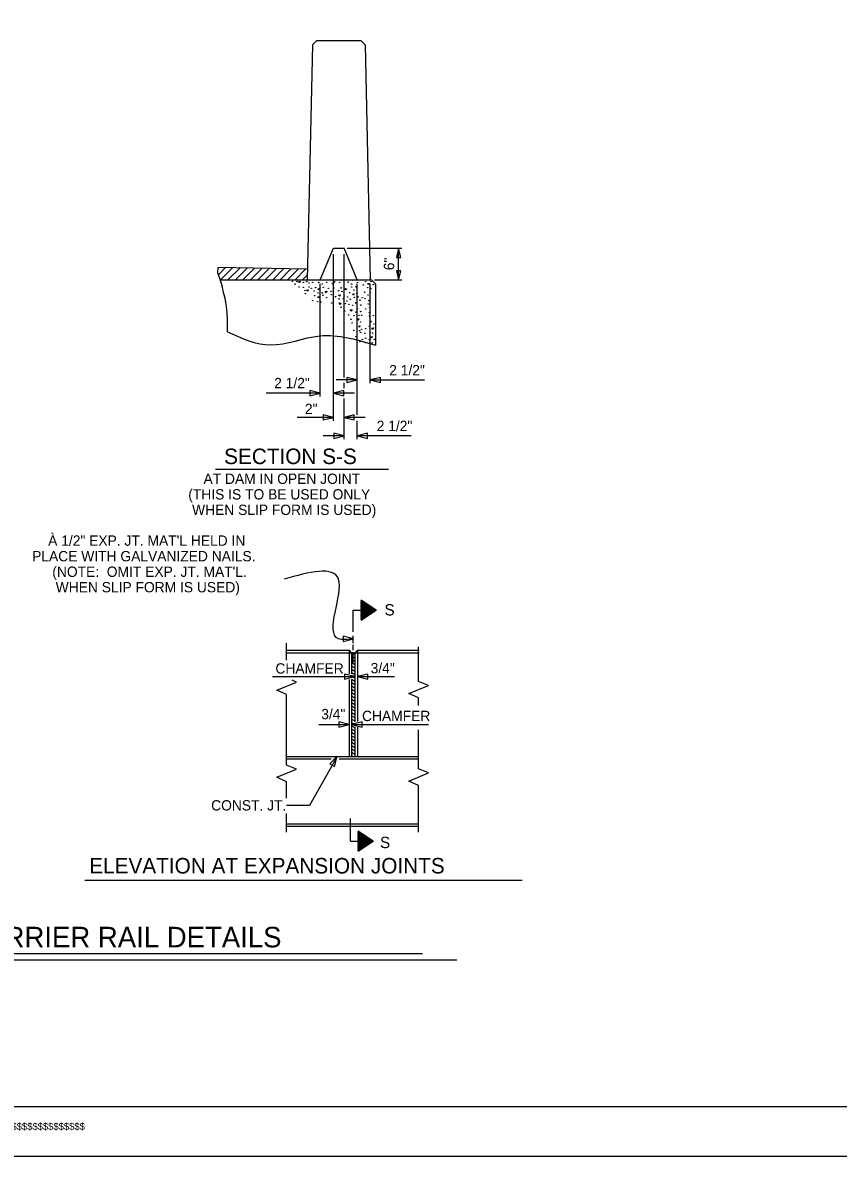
# Model space of a CAD drawing. Extents: x -38 to 94, y -165 to 80.
# Drawn here: x 62.97 to 72.87, y -165.04 to -151.27 of the extents above; entities that cross this region are included whole.
import ezdxf

# ---------------------------------------------------------------- set-up
doc = ezdxf.new("R2010")
doc.units = 0
for name, color, linetype in [('Arrowhead Terminators', 7, 'Continuous'), ('Box Beam', 7, 'Continuous'), ('Cored Slab Unit CELL', 7, 'Continuous'), ('Dimension Lines', 7, 'Continuous'), ('Mis Center Lines', 7, 'Continuous'), ('Mis Object Lines', 7, 'Continuous'), ('Miscellaneous Lines', 7, 'Continuous'), ('Plan Sheet CELL', 7, 'Continuous'), ('Plot Label CELL', 7, 'Continuous'), ('Plot Shape CELL', 7, 'Continuous'), ('Subtitle Text', 7, 'Continuous'), ('Sup Concrete Girder Lines', 7, 'Continuous'), ('Text', 7, 'Continuous'), ('Title Text', 7, 'Continuous'), ('User Information Notes', 7, 'Continuous')]:
    doc.layers.add(name, color=color, linetype=linetype)

msp = doc.modelspace()

# ---------------------------------------------------------------- linework, layer by layer
at = {"layer": 'Arrowhead Terminators'}
for points in [[(67.533, -154.009), (67.506, -154.118), (67.56, -154.118)], [(67.533, -154.391), (67.56, -154.282), (67.506, -154.282)], [(67.03, -155.607), (66.905, -155.576), (66.905, -155.638)], [(67.189, -155.607), (67.314, -155.638), (67.314, -155.576)], [(66.582, -155.768), (66.457, -155.736), (66.457, -155.799)], [(66.742, -155.768), (66.867, -155.799), (66.867, -155.736)], [(66.742, -156.061), (66.617, -156.03), (66.617, -156.093)], [(66.87, -156.061), (66.995, -156.093), (66.995, -156.03)], [(66.87, -156.286), (66.745, -156.255), (66.745, -156.318)], [(67.03, -156.286), (67.155, -156.318), (67.155, -156.255)], [(66.987, -158.751), (66.861, -158.72), (66.861, -158.783)], [(67.003, -159.211), (66.878, -159.18), (66.878, -159.242)], [(67.033, -159.211), (67.158, -159.242), (67.158, -159.18)], [(66.933, -159.791), (66.807, -159.76), (66.807, -159.823)], [(66.963, -159.791), (67.089, -159.823), (67.089, -159.76)], [(66.788, -160.177), (66.699, -160.271), (66.753, -160.302)]]:
    msp.add_lwpolyline(points, close=True, dxfattribs=at)
at = {"layer": 'Box Beam'}
for p, q in [((66.172, -160.18), (66.963, -160.18)), ((66.172, -160.21), (66.716, -160.21)), ((66.81, -160.21), (67.773, -160.21)), ((66.963, -160.18), (67.003, -160.18)), ((67.003, -160.18), (67.773, -160.18)), ((66.172, -160.997), (67.773, -160.997)), ((66.172, -161.027), (67.773, -161.027))]:
    msp.add_line(p, q, dxfattribs=at)
at = {"layer": 'Cored Slab Unit CELL'}
for p, q in [((66.486, -151.535), (66.423, -154.391)), ((66.534, -151.487), (66.486, -151.535)), ((67.077, -151.487), (66.534, -151.487)), ((67.077, -151.487), (67.125, -151.535)), ((67.125, -151.535), (67.189, -154.391))]:
    msp.add_line(p, q, dxfattribs=at)
at = {"layer": 'Dimension Lines'}
for p, q in [((66.742, -156.102), (66.742, -154.079)), ((66.87, -155.576), (66.87, -154.079)), ((66.91, -154.007), (67.572, -154.007)), ((67.533, -154.391), (67.533, -154.009)), ((66.582, -155.808), (66.582, -154.439)), ((67.03, -156.03), (67.03, -154.439)), ((67.189, -155.647), (67.189, -154.439)), ((67.241, -154.391), (67.572, -154.391)), ((67.03, -155.607), (66.774, -155.607)), ((67.189, -155.607), (67.847, -155.607)), ((66.87, -155.705), (66.87, -155.643)), ((66.582, -155.768), (65.924, -155.768)), ((66.998, -155.768), (66.742, -155.768)), ((66.87, -156.327), (66.87, -155.831)), ((66.742, -156.061), (66.303, -156.061)), ((67.126, -156.061), (66.87, -156.061)), ((67.03, -156.327), (67.03, -156.105)), ((66.87, -156.286), (66.617, -156.286)), ((67.687, -156.286), (67.03, -156.286)), ((66.983, -158.403), (67.26, -158.403)), ((66.983, -158.668), (66.983, -158.403)), ((66.003, -159.211), (67.003, -159.211)), ((67.033, -159.211), (67.484, -159.211)), ((66.565, -159.791), (66.933, -159.791)), ((66.963, -159.791), (67.896, -159.791)), ((66.948, -161.211), (66.948, -160.935)), ((66.948, -161.211), (67.225, -161.211))]:
    msp.add_line(p, q, dxfattribs=at)
for points in [[(67.077, -158.524), (67.26, -158.403), (67.077, -158.517), (67.077, -158.509), (67.26, -158.403), (67.077, -158.502), (67.077, -158.494), (67.26, -158.403), (67.077, -158.486), (67.077, -158.479), (67.26, -158.403), (67.077, -158.471), (67.077, -158.464), (67.26, -158.403), (67.077, -158.456), (67.077, -158.448), (67.26, -158.403), (67.077, -158.441), (67.077, -158.433), (67.26, -158.403), (67.077, -158.425), (67.077, -158.418), (67.26, -158.403), (67.077, -158.41), (67.077, -158.395), (67.26, -158.403), (67.077, -158.387), (67.077, -158.38), (67.26, -158.403), (67.077, -158.372), (67.077, -158.364), (67.26, -158.403), (67.077, -158.357), (67.077, -158.349), (67.26, -158.403), (67.077, -158.342), (67.077, -158.334), (67.26, -158.403), (67.077, -158.326), (67.077, -158.319), (67.26, -158.403), (67.077, -158.311), (67.077, -158.304), (67.26, -158.403), (67.077, -158.296), (67.077, -158.288), (67.26, -158.403), (67.077, -158.281), (67.077, -158.524), (67.26, -158.403), (67.077, -158.517)], [(66.788, -160.18), (66.449, -160.778), (66.172, -160.778)], [(67.042, -161.332), (67.225, -161.211), (67.042, -161.325), (67.042, -161.317), (67.225, -161.211), (67.042, -161.31), (67.042, -161.302), (67.225, -161.211), (67.042, -161.294), (67.042, -161.287), (67.225, -161.211), (67.042, -161.279), (67.042, -161.272), (67.225, -161.211), (67.042, -161.264), (67.042, -161.256), (67.225, -161.211), (67.042, -161.249), (67.042, -161.241), (67.225, -161.211), (67.042, -161.234), (67.042, -161.226), (67.225, -161.211), (67.042, -161.218), (67.042, -161.203), (67.225, -161.211), (67.042, -161.195), (67.042, -161.188), (67.225, -161.211), (67.042, -161.18), (67.042, -161.173), (67.225, -161.211), (67.042, -161.165), (67.042, -161.157), (67.225, -161.211), (67.042, -161.15), (67.042, -161.142), (67.225, -161.211), (67.042, -161.135), (67.042, -161.127), (67.225, -161.211), (67.042, -161.119), (67.042, -161.112), (67.225, -161.211), (67.042, -161.104), (67.042, -161.097), (67.225, -161.211), (67.042, -161.089), (67.042, -161.332), (67.225, -161.211), (67.042, -161.325)]]:
    msp.add_lwpolyline(points, dxfattribs=at)
msp.add_spline([(66.983, -158.751), (66.804, -158.751), (66.804, -158.025), (66.145, -158.025)], degree=3, dxfattribs=at)
at = {"layer": 'Mis Center Lines'}
for p, q in [((66.983, -158.803), (66.983, -158.715)), ((66.983, -158.888), (66.983, -158.826)), ((66.983, -159.038), (66.983, -158.912))]:
    msp.add_line(p, q, dxfattribs=at)
at = {"layer": 'Mis Object Lines'}
for p, q in [((66.582, -154.391), (66.742, -154.007)), ((66.742, -154.007), (66.87, -154.007)), ((67.03, -154.391), (66.87, -154.007)), ((66.172, -158.89), (66.932, -158.89)), ((66.963, -158.92), (66.932, -158.89)), ((66.932, -158.89), (66.932, -159.175)), ((67.003, -158.92), (67.034, -158.89)), ((67.033, -158.89), (67.033, -159.756)), ((67.034, -158.89), (67.781, -158.89)), ((66.172, -158.92), (66.963, -158.92)), ((66.963, -158.92), (66.963, -159.177)), ((66.963, -158.92), (66.963, -158.92)), ((66.963, -158.92), (67.003, -158.943)), ((66.963, -158.92), (67.003, -158.92)), ((66.963, -158.96), (67.003, -158.983)), ((66.963, -159.001), (67.003, -159.024)), ((66.963, -159.041), (67.003, -159.064)), ((67.003, -158.92), (67.781, -158.92)), ((67.003, -158.92), (67.003, -159.76)), ((66.963, -159.081), (67.003, -159.104)), ((66.963, -159.122), (67.003, -159.145)), ((66.963, -159.162), (67.003, -159.185)), ((66.932, -159.247), (66.932, -160.181)), ((66.963, -159.202), (67.003, -159.225)), ((66.963, -159.242), (67.003, -159.265)), ((66.963, -159.246), (66.963, -160.18)), ((66.963, -159.283), (67.003, -159.306)), ((66.963, -159.323), (67.003, -159.346)), ((66.963, -159.363), (67.003, -159.386)), ((66.963, -159.404), (67.003, -159.427)), ((66.963, -159.444), (67.003, -159.467)), ((66.963, -159.484), (67.003, -159.507)), ((66.963, -159.525), (67.003, -159.548)), ((66.963, -159.565), (67.003, -159.588)), ((66.963, -159.605), (67.003, -159.628)), ((66.963, -159.645), (67.003, -159.669)), ((66.963, -159.686), (67.003, -159.709)), ((66.963, -159.726), (67.003, -159.749)), ((66.963, -159.766), (67.003, -159.789)), ((66.963, -159.807), (67.003, -159.83)), ((66.963, -159.847), (67.003, -159.87)), ((67.003, -159.822), (67.003, -160.18)), ((67.033, -159.824), (67.033, -160.18)), ((66.963, -159.887), (67.003, -159.91)), ((66.963, -159.928), (67.003, -159.951)), ((66.963, -159.968), (67.003, -159.991)), ((66.963, -160.008), (67.003, -160.031)), ((66.963, -160.048), (67.003, -160.072)), ((66.963, -160.089), (67.003, -160.112)), ((66.963, -160.129), (67.003, -160.152)), ((66.963, -160.169), (66.981, -160.18))]:
    msp.add_line(p, q, dxfattribs=at)
for points in [[(66.172, -159.01), (66.172, -158.806)], [(67.773, -159.553), (67.773, -159.47), (67.658, -159.417), (67.894, -159.318), (67.773, -159.268), (67.773, -158.848)], [(66.172, -159.511), (66.172, -159.428), (66.056, -159.375), (66.293, -159.276), (66.242, -159.255)], [(66.172, -160.688), (66.172, -160.487), (66.056, -160.434), (66.293, -160.335), (66.172, -160.285), (66.172, -159.507)], [(67.773, -159.56), (67.773, -159.553)], [(67.773, -161.099), (67.773, -160.533), (67.658, -160.48), (67.894, -160.381), (67.773, -160.331), (67.773, -159.859)], [(66.172, -161.099), (66.172, -160.874)]]:
    msp.add_lwpolyline(points, dxfattribs=at)
at = {"layer": 'Miscellaneous Lines'}
for p, q in [((66.423, -154.263), (65.337, -154.241)), ((65.344, -154.328), (65.427, -154.245)), ((65.371, -154.391), (65.517, -154.245)), ((65.461, -154.391), (65.606, -154.247)), ((65.552, -154.391), (65.694, -154.248)), ((65.642, -154.391), (65.783, -154.25)), ((65.733, -154.391), (65.871, -154.252)), ((65.823, -154.391), (65.96, -154.254)), ((65.913, -154.391), (66.049, -154.255)), ((66.004, -154.391), (66.137, -154.257)), ((66.094, -154.391), (66.226, -154.259)), ((66.184, -154.391), (66.314, -154.261)), ((66.275, -154.391), (66.403, -154.263)), ((66.365, -154.391), (66.423, -154.333))]:
    msp.add_line(p, q, dxfattribs=at)
msp.add_lwpolyline([(65.337, -154.241), (65.335, -154.307), (65.368, -154.391)], dxfattribs=at)
at = {"layer": 'Plan Sheet CELL'}
msp.add_line((55.987, -164.432), (87.987, -164.432), dxfattribs=at)
at = {"layer": 'Plot Shape CELL'}
msp.add_lwpolyline([(54.933, -143.038), (87.996, -143.038), (87.996, -165.038), (54.933, -165.038)], close=True, dxfattribs=at)
at = {"layer": 'Subtitle Text'}
for p, q in [((65.309, -156.692), (67.411, -156.692)), ((63.721, -161.682), (69.032, -161.682))]:
    msp.add_line(p, q, dxfattribs=at)
at = {"layer": 'Sup Concrete Girder Lines'}
for points in [[(65.368, -154.391), (66.104, -154.391), (67.205, -154.391), (67.253, -154.439), (67.253, -155.185)], [(66.33, -154.426), (66.317, -154.413), (66.337, -154.408), (66.33, -154.426)], [(66.566, -154.514), (66.551, -154.501), (66.571, -154.494), (66.566, -154.514)], [(66.75, -154.426), (66.743, -154.408), (66.758, -154.411), (66.75, -154.426)], [(66.891, -154.517), (66.883, -154.496), (66.899, -154.499), (66.891, -154.517)], [(67.168, -154.451), (67.16, -154.434), (67.175, -154.436), (67.168, -154.451)], [(66.431, -154.529), (66.415, -154.517), (66.436, -154.512), (66.431, -154.529)], [(66.561, -154.615), (66.551, -154.597), (66.569, -154.597), (66.561, -154.615)], [(66.654, -154.547), (66.642, -154.534), (66.66, -154.529), (66.654, -154.547)], [(66.818, -154.589), (66.803, -154.577), (66.823, -154.572), (66.818, -154.589)], [(66.987, -154.577), (66.974, -154.564), (66.994, -154.559), (66.987, -154.577)], [(66.823, -154.693), (66.813, -154.672), (66.831, -154.675), (66.823, -154.693)], [(66.959, -154.773), (66.944, -154.761), (66.964, -154.753), (66.959, -154.773)], [(67.019, -154.678), (67.007, -154.665), (67.024, -154.66), (67.019, -154.678)], [(67.042, -154.884), (67.032, -154.864), (67.049, -154.866), (67.042, -154.884)], [(67.188, -154.907), (67.188, -154.889), (67.205, -154.896), (67.188, -154.907)], [(67.057, -154.967), (67.044, -154.954), (67.062, -154.949), (67.057, -154.967)], [(67.22, -154.992), (67.208, -154.979), (67.228, -154.972), (67.22, -154.992)], [(67.065, -155.148), (67.057, -155.13), (67.075, -155.13), (67.065, -155.148)], [(67.205, -155.1), (67.195, -155.088), (67.213, -155.08), (67.205, -155.1)]]:
    msp.add_lwpolyline(points, dxfattribs=at)
for centre in [(66.242, -154.409), (66.275, -154.443), (66.299, -154.411), (66.325, -154.478), (66.377, -154.423), (66.377, -154.481), (66.418, -154.411), (66.444, -154.429), (66.444, -154.478), (66.472, -154.494), (66.49, -154.42), (66.526, -154.484), (66.564, -154.423), (66.605, -154.441), (66.619, -154.483), (66.661, -154.42), (66.679, -154.493), (66.73, -154.437), (66.749, -154.491), (66.817, -154.421), (66.835, -154.488), (66.921, -154.419), (66.963, -154.479), (66.964, -154.443), (66.97, -154.398), (67.015, -154.475), (67.032, -154.421), (67.104, -154.452), (67.133, -154.413), (67.158, -154.487), (67.199, -154.411), (67.198, -154.498), (67.226, -154.448), (66.397, -154.517), (66.402, -154.558), (66.49, -154.644), (66.506, -154.527), (66.512, -154.583), (66.553, -154.55), (66.605, -154.549), (66.615, -154.577), (66.66, -154.607), (66.712, -154.53), (66.715, -154.572), (66.742, -154.538), (66.767, -154.597), (66.805, -154.524), (66.811, -154.622), (66.845, -154.532), (66.863, -154.619), (66.868, -154.586), (66.906, -154.647), (66.914, -154.599), (66.937, -154.546), (66.946, -154.626), (66.992, -154.514), (66.997, -154.604), (67.026, -154.556), (67.041, -154.597), (67.065, -154.637), (67.091, -154.607), (67.121, -154.54), (67.126, -154.619), (67.162, -154.576), (67.172, -154.642), (67.19, -154.542), (66.549, -154.657), (66.589, -154.662), (66.721, -154.671), (66.835, -154.723), (66.88, -154.769), (66.885, -154.681), (66.93, -154.689), (66.975, -154.701), (67.016, -154.783), (67.031, -154.738), (67.074, -154.698), (67.074, -154.776), (67.134, -154.746), (67.164, -154.685), (67.181, -154.73), (66.925, -154.818), (66.956, -154.869), (66.968, -154.913), (66.991, -154.827), (67.051, -154.823), (67.073, -154.903), (67.083, -154.822), (67.178, -154.79), (67.179, -154.832), (67.227, -154.825), (66.986, -155.004), (67.059, -155.01), (67.073, -155.028), (67.085, -154.993), (67.123, -155.041), (67.134, -154.984), (67.178, -154.955), (67.187, -155.024), (67.216, -155.038), (67.233, -154.928), (67.015, -155.082), (67.093, -155.115), (67.129, -155.153), (67.132, -155.1), (67.176, -155.117), (67.18, -155.163), (67.212, -155.156), (67.239, -155.115)]:
    msp.add_circle(centre, 0.00279, dxfattribs=at)
for points in [[(65.455, -155.021), (65.448, -154.756), (65.368, -154.391)], [(65.455, -155.021), (65.978, -155.181), (66.576, -155.071), (67.253, -155.185)]]:
    msp.add_spline(points, degree=3, dxfattribs=at)
at = {"layer": 'Title Text'}
for p, q in [((67.823, -162.578), (58.317, -162.578)), ((68.238, -162.655), (57.902, -162.655))]:
    msp.add_line(p, q, dxfattribs=at)
at = {"layer": 'User Information Notes'}
msp.add_line((67.253, -154.391), (67.253, -154.391), dxfattribs=at)

# ---------------------------------------------------------------- texts
at = {"layer": 'Plot Label CELL'}
msp.add_text('$$$$$$$$$$$$$$$$$$$$$$$DGN$$$$$$$$$$$$$$$$$$$$$$$', height=0.08556, dxfattribs=at).set_placement((60.542, -164.717))
at = {"layer": 'Subtitle Text'}
for s, height, p in [('SECTION S-S', 0.1886, (65.414, -156.629)), ('ELEVATION AT EXPANSION JOINTS', 0.18863, (63.776, -161.602))]:
    msp.add_text(s, height=height, dxfattribs=at).set_placement(p)
at = {"layer": 'Text'}
msp.add_text('6"', height=0.1254, rotation=90, dxfattribs=at).set_placement((67.479, -154.274))
for s, height, p in [('2 1/2"', 0.1254, (67.419, -155.551)), ('2 1/2"', 0.1254, (66.022, -155.707)), ('2"', 0.1254, (66.395, -156.021)), ('2 1/2"', 0.1254, (67.267, -156.228)), ('AT DAM IN OPEN JOINT', 0.12544, (65.164, -156.87)), ('(THIS IS TO BE USED ONLY', 0.12544, (64.979, -157.059)), ('WHEN SLIP FORM IS USED)', 0.12544, (65.025, -157.247)), ('À 1/2" EXP. JT. MAT\'L HELD IN', 0.12544, (63.278, -157.621)), ('PLACE WITH GALVANIZED NAILS.', 0.12544, (63.083, -157.81)), ("(NOTE:  OMIT EXP. JT. MAT'L.", 0.12544, (63.328, -157.999)), ('WHEN SLIP FORM IS USED)', 0.12544, (63.369, -158.187)), ('S', 0.138, (67.362, -158.468)), ('CHAMFER', 0.1254, (66.037, -159.174)), ('3/4"', 0.1254, (67.194, -159.17)), ('3/4"', 0.1254, (66.594, -159.728)), ('CHAMFER', 0.1254, (67.089, -159.751)), ('CONST. JT.', 0.1254, (65.257, -160.837)), ('S', 0.138, (67.307, -161.294))]:
    msp.add_text(s, height=height, dxfattribs=at).set_placement(p)
at = {"layer": 'Title Text'}
msp.add_text('VERTICAL CONCRETE BARRIER RAIL DETAILS', height=0.25, dxfattribs=at).set_placement((58.606, -162.5))

doc.saveas('drawing.dxf')
